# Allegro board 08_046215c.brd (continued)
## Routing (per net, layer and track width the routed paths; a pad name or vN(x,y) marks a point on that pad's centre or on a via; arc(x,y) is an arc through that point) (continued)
ADCLK914OUT: length 3.6
  TOP w0.305: U16.11 14.48,20.37 14.41,20.44 R625.1 14.41,23.33 C39.1
ADCLK914VCC: length 5.6
  TOP w0.254: R625.2 v1(15.05,21.99) ; U16.8 v1(16.88,19.13) 17.06,18.95 C654.1 ; U16.13 v1(12.58,19.13)
  TOP w0.305: C655.1 12.57,19.14 v1(12.58,19.13)
  BOTTOM w0.254: 11.43,7.32 v1(11.23,7.32)
  BOTTOM w0.508: 11.43,7.32 12.51,8.41 12.51,8.47 E68.2
ADF4355_VDD_3V3: length 16.4
  TOP w0.203: R619.2 31.37,9.87 v4(31.5,9.99) ; v1(24,16.09) 24,15.27 24.17,15.1 24.17,15.04 24.26,14.94 U15.5
  TOP w0.254: U15.16 22.06,10.08 v4(21.72,9.74) ; U18.2 12.82,12.54 12.15,13.21 11.85,13.21 ; v1(27.79,11.11) 27.72,11.11 27.64,11.19 27,11.19 U15.27 ; 11.85,13.21 C669.2 ; 11.85,13.21 v4(12.19,13.55)
  TOP w0.305: R611.2 v4(21.21,18.12)
  L10_SIGNAL w0.33: 43.26,14.65 JP1.2 ; JP1.2 44.87,14.65 ; JP1.2 44.87,16.26 ; JP1.2 43.26,16.26
  BOTTOM w0.254: C614.1 C616.1 26.61,10.91 26.96,11.26 27.56,11.26 27.71,11.11 v1(27.79,11.11)
  vias: v4(12.19,12.91)
ADF4355_VRF_3V3: length 1.7
  TOP w0.203: v4(21.21,14.12) 21.21,13.42 21.48,13.15
  TOP w0.305: U15.10 21.48,13.15
  vias: v4(16.26,11.01) v4(16.26,9.99)
ADF4355_VVCO_5V: length 10.2
  TOP w0.254: U15.19 23.76,8.74 23.37,8.34 C643.1 ; C618.1 23.05,16.03 23.5,15.58 23.5,15.2 23.76,14.93 U15.6
  TOP w0.305: U17.2 38.36,5.51 C668.2 ; C636.1 v4(22.1,8.47) 22.76,9.13 U15.17 ; C618.1 C619.1 v4(21.15,16.03)
  TOP w0.508: v4(39.37,5.29) 39.34,5.29 39.28,5.23 38.7,5.23 38.64,5.29 38.57,5.29 C668.2
  vias: v4(38.99,5.93)
ADF4355OUTA: length 1.6
  TOP w0.305: U16.2 14.48,15.64 C632.2
ADF4355OUTAB: length 1.6
  TOP w0.305: C633.2 13.98,15.66 U16.1
ADF4355OUTB: length 2.3
  TOP w0.305: U9.7 25.91,3.77 25.15,4.53 C638.2
ADF4355OUTBB: length 2.3
  TOP w0.305: U9.5 26.04,6.31 25.15,5.42 C639.2
ADP5054_1V2: length 5.7
  TOP w0.203: v6(29.83,40.58) U1.K9 v6(29.83,39.58) U1.K7 v6(29.83,38.58) ; v6(28.33,40.58) U1.G9 ; v6(28.33,39.08) U1.G6
  TOP w0.508: C525.1 v4(48.13,43.01)
  BOTTOM w0.254: C550.1 29.9,38.58 v6(29.83,38.58) ; C2.1 30,40.76 v6(29.83,40.58) ; C3.1 28.33,40.65 v6(28.33,40.58) ; v6(28.33,39.08) 28.33,38.52 C538.1 ; C544.1 v6(29.83,39.58)
  vias: v4(53.85,36.92) v4(54.1,37.68) v4(54.48,36.54)
ADP5054_1V5: length 2.7
  BOTTOM w0.508: 41.5,42.86 E1.2 v4(40.64,43.78) v4(40.64,44.66)
  vias: v4(22.61,60.92) v4(23.62,60.92) v4(24.13,60.16) v4(24.64,60.92) v4(31.88,60.79) v4(32.51,59.9) v4(33.02,60.79) v4(33.66,59.9) v4(38.35,43.64) v4(38.48,44.79) v4(41.53,42.89)
ADP5054_3V8: length 12.8
  TOP w0.508: 15.37,4.09 v4(16.19,4.09)
  L3_SIGNAL w0.508: v2(15.11,60.54) 13.46,60.54 12.83,59.9 v4(5.59,59.9)
  L11_GROUND w0.508: v3(15.11,61.3) v2(15.11,60.54)
  BOTTOM w0.508: 56.52,18.91 v4(56.52,18.25) ; R63.2 v3(15.11,61.3)
  vias: v4(5.59,60.67) v4(6.35,60.67) v4(9.02,15.45) v4(16.13,4.66) v4(39.24,63.08) v4(42.04,63.59) v4(55.44,18.63) v4(55.75,17.74) v4(56.64,17.36)
ADP5054_5V5: length 3.4
  TOP w0.508: 39.56,12.28 v4(40.26,12.28)
  BOTTOM w0.508: E31.1 v4(32.26,13.68) ; 36.09,22.69 34.42,22.69 v4(34.42,23.58)
  vias: v4(33.66,23.71) v4(40.26,12.91)
ADP5073_2V2: length 21
  BOTTOM w0.508: 36.45,51.52 35.05,52.92 35.05,53.68 32.77,55.97 29.59,55.97 25.4,60.16 25.4,61.56 24.38,62.57 R443.1
CLK_N: length 2.9
  TOP w0.254: U1.D1 26.83,35.52 arc(26.88,35.26) 27.03,35.03 27.18,34.89
  TOP w0.508: 27.18,34.89 27.37,34.69 arc(27.74,34.14) C349.2
CLK_P: length 2.9
  TOP w0.254: U1.C1 26.33,35.59 arc(26.25,35.21) 26.04,34.89
  TOP w0.508: 26.04,34.89 25.75,34.6 arc(25.42,34.1) C348.2
CPOUT: length 8.6
  TOP w0.203: U15.7 23.24,14.37 23.24,14.82 22.86,15.2 22.34,15.2 v1(22.09,14.95)
  BOTTOM w0.203: v1(22.09,14.95) 22.09,14.07 arc(22,13.59) 21.72,13.17 21.06,12.51 arc(20.66,12.25) 20.19,12.15 C61.2 C62.1 18.54,12.15 R62.1
CS1: length 67.2
  TOP w0.203: U21.14 57.29,45.31 56.29,44.31 56.29,44.06 v1(56.11,43.88) ; U20.20 v1(52.86,56.25)
  L3_SIGNAL w0.203: v1(56.11,43.88) 56.11,43.92 56.13,43.95 56.13,44.04 56.29,44.19 56.29,44.31 58.29,46.32 58.29,52.67 55.24,55.71 53.4,55.71 v1(52.86,56.25) 52.86,57.46 51.94,58.38 47.89,58.38 47.22,57.71 47.22,56.2 46.42,55.41 37.03,55.41 34.16,52.54 30.48,52.54 v1(28.7,50.76)
  L10_SIGNAL w0.203: v1(52.86,56.25) 52.86,57.97 50.93,59.9 50.93,62.25 50.61,62.57 49.4,62.57 46.84,65.14 44.17,65.14 P2.2
  BOTTOM w0.203: R19.1 v1(28.7,50.76)
CS2: length 79.5
  TOP w0.203: U22.11 63,43 62.48,43.52 61.47,43.52 61.15,43.84 v1(60.77,43.84) ; R316.1 52.5,7.25 v1(52.58,7.33) 52.58,5.73 52.45,5.6 52.45,5.29 R38.1 ; U20.10 v1(47.36,60.94)
  L10_SIGNAL w0.203: v1(60.77,43.84) 61.85,44.92 61.85,48.86 59.05,51.65 59.05,53.17 57.02,55.21 51.69,55.21 49.4,57.49 49.4,58.25 48.39,59.27 48.39,60.54 47.99,60.94 v1(47.36,60.94)
  BOTTOM w0.203: v1(60.77,43.84) 60.77,42.7 60.33,42.26
  BOTTOM w0.254: 60.33,42.26 60.33,39.58 60.96,38.95 60.96,30.95 60.33,30.31 60.33,13.04 57.66,10.37 54.36,10.37 52.58,8.6 v1(52.58,7.33)
CS3: length 88.9
  TOP w0.203: v1(51.56,64.22) U20.4 ; R615.1 v1(25.02,16.98) ; v1(63.75,41.87) 63.88,42 64.64,42 64.65,42 U22.13
  L3_SIGNAL w0.203: v1(51.56,64.22) 52.07,63.71 52.07,63.33 54.99,60.41 54.99,59.59 63.06,51.52 63.06,42.56 v1(63.75,41.87)
  L10_SIGNAL w0.203: v1(25.02,16.98) 25.02,18.25 28.07,21.3 30.73,21.3 31.71,22.28 46.05,22.28 46.74,21.59 56.26,21.59 63.12,28.45 63.12,33.36 64.39,34.63 64.39,41.24 v1(63.75,41.87)
DAC_CSB: length 5.8
  TOP w0.203: U1.G15 v6(28.33,44.53)
  L3_SIGNAL w0.203: v6(28.33,44.53) 28.33,47.72 v6(28.7,48.09)
  BOTTOM w0.203: R19.2 v6(28.7,48.09)
DAC_SCLK: length 7.4
  L3_SIGNAL w0.203: v6(29.33,42.08) 29.33,42.47 29.42,42.56 29.42,42.75 29.62,42.95 29.62,43.04 29.84,43.27 29.84,46.82 v6(30.99,47.97)
  BOTTOM w0.203: R23.2 30.99,48.47 v6(30.99,47.97)
DAC_SDIO: length 7.8
  L10_SIGNAL w0.203: v6(29.83,42.08) 29.93,42.08 30.42,42.57 30.42,42.75 30.73,43.06 30.73,43.33 30.74,43.33 30.74,43.67 30.73,43.67 30.73,45.43 v6(30.99,45.68)
  BOTTOM w0.203: R22.2 32.51,47.2 v6(30.99,45.68)
DAC_SDO: length 7.2
  L3_SIGNAL w0.203: v6(29.97,48.09) 28.83,46.95 28.83,44.28 28.32,43.78 28.32,42.89 28.62,42.58 v6(28.83,42.58)
  BOTTOM w0.203: v6(29.97,48.09) R20.2
DAC_TXEN_0: length 7.7
  TOP w0.203: v1(33.66,35.27) 34.34,35.27 R8.2
  L10_SIGNAL w0.203: v1(33.66,35.27) 32.77,34.38 30.92,34.38 29.92,35.38 29.92,35.49 v6(28.83,36.58)
  BOTTOM w0.203: R18.2 v1(33.66,35.27)
DIV2IN: length 1.4
  TOP w0.203: C341.2 46.74,6.35 46.87,6.48 U7.21
DIV2INB: length 1.4
  TOP w0.203: U7.22 47.37,6.44 47.5,6.31 C340.2
DL1: length 2.9
  BOTTOM w0.203: Q1.2 46.23,35.39 46.73,34.89 U10.31
DL2: length 5.7
  L10_SIGNAL w0.203: v1(46.23,38.19) 46.23,34.25 v1(45.97,34)
  BOTTOM w0.203: Q1.5 v1(46.23,38.19) ; U10.29 45.73,33.75 v1(45.97,34)
EN: length 32.1
  TOP w0.203: v5(11.4,64.12) Q3.PAD2 10.96,63.94 Q3.3 11.56,62.62 R51.1 ; v1(35.94,66.76) 35.94,66.13 35.37,65.55 U4.3
  L2_GROUND w0.203: v5(11.4,64.12) v2(11.94,63.59)
  L3_SIGNAL w0.203: v2(11.94,63.59) 12.19,63.33 13.59,63.33 14.1,63.84 15.75,63.84 16.89,62.7 20.28,62.7 20.5,62.93 28.3,62.93 32.13,66.76 v1(35.94,66.76)
FMC_CS1: length 5.6
  TOP w0.203: U21.3 61.73,45.31 62.36,45.93 v1(65.02,45.93)
  BOTTOM w0.203: P1.H11 65,45.93 v1(65.02,45.93)
FMC_CS2: length 4.8
  TOP w0.203: v1(68.88,45.86) 68.19,45.17 68.19,44.04 68.33,43.89 68.34,43.89 68.57,43.66 68.57,43.25 68.31,43 U22.6
  BOTTOM w0.203: P1.D11 v1(68.88,45.86)
FMC_CS3: length 2
  TOP w0.203: U22.4 68.83,42 v1(68.88,42.05)
  BOTTOM w0.203: P1.D14 v1(68.88,42.05)
FMC_HMC849VCTL: length 2.3
  TOP w0.203: U22.3 68.23,41.5 68.57,41.16 68.57,41.1 v1(68.88,40.78)
  BOTTOM w0.203: P1.D15 v1(68.88,40.78)
FMC_MISO: length 4.6
  TOP w0.203: v1(63.8,47.13) 62.03,47.13 61.21,46.31 U21.5
  BOTTOM w0.203: P1.H10 v1(63.8,47.13)
FMC_MOSI: length 6
  TOP w0.203: U21.4 61.35,45.81 62.13,46.6 64.19,46.6 64.21,46.62 64.55,46.62 v1(65.07,47.13)
  BOTTOM w0.203: P1.G10 v1(65.07,47.13)
FMC_SCK: length 6.1
  TOP w0.203: v1(65.07,48.4) 64.33,47.67 61.93,47.67 61.08,46.81 U21.6
  BOTTOM w0.254: P1.G9 v1(65.07,48.4)
FMC_SCL: length 36.3
  TOP w0.203: U23.6 71.81,54.51 73.79,52.54 73.79,24.09 73.28,23.58 72,23.58 v1(71.42,23)
  BOTTOM w0.203: P1.C30 v1(71.42,23)
FMC_SDA: length 37.6
  TOP w0.203: v1(70.15,23) 72,24.85 72.77,24.85 73.28,25.36 73.28,52.16 71.16,54.28 U23.5
  BOTTOM w0.203: v1(70.15,23) 70.15,21.73 P1.C31
FMC_SPI_EN: length 51.8
  TOP w0.203: U20.6 v1(50.26,64.19) ; v1(66.3,44.66) 66.17,44.66 65.6,45.23 65.6,48.62 65.24,48.98 64.26,48.98 63.5,49.74 59.31,49.74 R73.2 58.93,49.36 U21.9
  TOP w0.254: 63.5,45.05 63.88,45.05 64.13,45.3 65.53,45.3 65.6,45.23 ; U22.9 v1(66.3,44.66)
  L3_SIGNAL w0.203: v1(66.3,44.66) 66.94,45.3 68.17,45.3 v1(68.88,44.59)
  L10_SIGNAL w0.203: v1(50.26,64.19) 51.31,65.24 53.59,65.24 55.83,63 56.11,63 56.76,62.36 56.76,61.39 61.26,56.88 61.26,53.38 63.12,51.52 63.12,46.06 63.88,45.3 65.66,45.3 v1(66.3,44.66)
  BOTTOM w0.203: P1.D12 v1(68.88,44.59)
FMC_TXEN_0: length 8.8
  TOP w0.203: v1(70.23,43.27) 69.22,43.27 68.45,42.5 U22.5
  BOTTOM w0.203: P1.H13 65.11,43.29 68.49,43.29 68.51,43.27 69.25,43.27 69.27,43.29 69.76,43.29 69.78,43.27 v1(70.23,43.27)
FMCA_VCC_12P0V: length 18.1
  TOP w0.508: v4(56.39,9.1) D1.C v4(57.67,7.7) ; TP41.1 59.82,7.2 C548.P
  TOP w0.635: 58.97,8.63 TP41.1 ; TP41.1 58.97,10.34 ; TP41.1 60.67,10.34
  L5_POWER w0.635: 59.01,10.29 TP41.1 ; TP41.1 59.01,8.68 ; TP41.1 60.62,10.29
  BOTTOM w0.508: v4(56.26,5.17) 56.26,3.39 ; v1(71.5,16.72) 70.8,16.02 P1.C35 ; v1(70.12,14.3) 70.78,13.63 P1.C37 ; FL1.1 v4(54.24,3.28)
  vias: v4(54.48,1.74) v4(54.61,4.79) v4(55.5,1.61)
GA0: length 49.9
  TOP w0.203: U23.1 73.11,58.42 74.8,56.73 74.8,54.95 74.3,54.44 74.3,18.5 73.15,17.36 70.85,17.36 v1(70.15,16.65)
  BOTTOM w0.254: P1.C34 v1(70.15,16.65)
GA1: length 56.4
  TOP w0.203: U23.2 72.46,63.01 v1(72.39,63.08)
  L10_SIGNAL w0.203: v1(72.39,63.08) 72.39,56.1 75.46,53.03 75.46,19.04 73.79,17.36 69.8,17.36 69.6,17.16 69.6,16.1 v1(68.88,15.38)
  BOTTOM w0.254: P1.D35 v1(68.88,15.38)
GBTCLK0_M2C_N: length 72.7
  TOP w0.127: C333.2 51.65,8.47 51.84,8.66 53.38,8.66 54.68,9.96 54.68,11.29 54.48,11.5 54.48,11.59 54.28,11.79 53.92,11.79 v6(53.7,12.01)
  L3_SIGNAL w0.127: v6(53.7,12.01) 53.94,11.77 72.14,11.77 72.64,12.28 72.64,13.3 73.66,14.31 73.66,52.03 71.66,54.03 69.65,54.03 69.53,54.02 69.53,54.02 69.4,54 v1(68.88,53.48)
  BOTTOM w0.203: P1.D5 v1(68.88,53.48)
GBTCLK0_M2C_P: length 72.7
  TOP w0.127: C334.2 51.65,9.1 51.84,8.91 53.28,8.91 54.43,10.07 54.43,11.19 54.23,11.39 54.23,11.49 54.18,11.54 53.93,11.54 v6(53.7,11.31)
  L3_SIGNAL w0.127: v1(68.88,54.75) 69.37,54.26 69.5,54.27 69.64,54.28 71.77,54.28 73.91,52.14 73.91,14.21 72.9,13.19 72.9,12.17 72.24,11.52 53.91,11.52 v6(53.7,11.31)
  BOTTOM w0.203: P1.D4 v1(68.88,54.75)
HMC365_VDD: length 0.8
  BOTTOM w0.254: U6.2 30.09,6.57 30.1,6.56
  vias: v1(32,7.45)
HMC365OUT: length 21.2
  TOP w0.127: C341.1 46.74,5.08 46.99,4.82 46.99,3.9 46.48,3.39 R37.2 46.61,2.63 arc(46.88,2.52) 46.99,2.25 46.99,1.99 arc(46.96,1.85) 46.88,1.74 46.68,1.54 arc(46.62,1.5) 46.56,1.48 35.81,1.48 arc(35.28,1.71) 35.05,2.25 35.05,3.3 arc(34.88,3.72) 34.45,3.9 arc(34.19,3.95) 33.96,4.1 33.27,4.79 arc(32.99,4.97) 32.66,5.04 U9.3
HMC365OUTB: length 21.6
  TOP w0.127: C340.1 47.5,5.08 47.24,4.82 47.24,3.9 47.75,3.39 47.75,2.63 47.62,2.63 arc(47.36,2.52) 47.24,2.25 47.24,1.99 arc(47.2,1.76) 47.06,1.56 46.86,1.36 arc(46.72,1.26) 46.56,1.23 35.81,1.23 arc(35.1,1.53) 34.8,2.25 34.8,3.3 arc(34.7,3.54) 34.45,3.64 arc(34.19,3.59) 33.96,3.44 33.55,3.03 arc(32.96,2.64) 32.27,2.5 U9.1
HMC849_VDD: length 2
  BOTTOM w0.203: E66.2 12.51,10.63
  BOTTOM w0.508: 12.51,10.63 12.51,11.58 v1(11.94,12.15)
  vias: v1(19.69,22.95)
HMC849VCTL: length 87.3
  TOP w0.203: U22.14 64.4,41.5 v1(63.75,40.85) ; R31.2 v1(22.23,24.22) ; U20.9 v1(47.65,61.59)
  L3_SIGNAL w0.203: v1(63.75,40.85) 61.85,42.76 61.85,50 52.58,59.27 49.66,59.27 49.15,59.78 49.15,60.57 48.13,61.59 v1(47.65,61.59)
  L10_SIGNAL w0.203: v1(63.75,40.85) 63.75,34.76 62.36,33.36 62.36,29.42 57.15,24.22 54.09,24.22 54.07,24.19 53.63,24.19 53.6,24.22 39.24,24.22 39.03,24.43 33.24,24.43 33.02,24.22 v1(22.23,24.22)
IRQB: length 9.7
  TOP w0.203: U1.G1 28.33,34.5 30.35,32.47 TP21.1 31.12,29.81 CR5.C
LTC2928_ON: length 66.2
  L10_SIGNAL w0.203: v2(41.02,29.42) 39.62,30.82 38.73,30.82 37.47,32.09 31.68,32.09 28.32,35.45 28.32,36.92 28.83,37.43 28.83,37.62 27.92,38.53 27.92,40.75 28.32,41.15 28.32,43.52 27.43,44.41 27.43,45.55 28.07,46.19 28.07,51.87 24.73,55.21 20.45,55.21 18.41,53.17 17.02,53.17 16.13,54.06 14.52,54.06 13.59,53.13 11.6,53.13 10.92,53.81 5.84,53.81 4.45,55.21 v1(2.54,55.21)
  L11_GROUND w0.203: v3(41.53,28.93) 41.52,28.93 v2(41.02,29.42)
  BOTTOM w0.203: R70.2 v1(2.54,55.21) ; U10.17 v3(41.53,28.93) 40.88,28.93 R416.1
LTC2928_ON_A: length 67.6
  L10_SIGNAL w0.203: v1(51.05,46.7) 45.59,46.7 42.29,50 42.29,55.59 41.15,56.73 38.48,56.73 35.81,54.06 35.81,51.27 34.04,49.49 32.77,49.49 31.88,50.38 31.88,51.4 30.1,53.17 28.57,53.17 26.04,55.71 17.14,55.71 16.64,55.21 14.52,55.21 12.83,53.51 11.98,53.51 11.05,54.44 5.97,54.44 4.06,56.35 v1(2.54,56.35)
  BOTTOM w0.203: v1(51.05,46.7) 51.19,46.57 U11.3 ; R71.2 v1(2.54,56.35)
MISO: length 45.7
  TOP w0.203: U21.12 56.76,46.31 v1(56.13,45.68) ; U20.19 v1(52.21,56.49)
  L3_SIGNAL w0.203: v1(29.97,50.76) 31.24,52.03 34.54,52.03 36.32,53.81 39.12,53.81 39.88,53.05 41.28,53.05 43.05,54.82 46.86,54.82 47.88,55.84 47.88,56.35 48.51,56.98 49.3,56.98 50.19,57.87 51.69,57.87 52.21,57.35 v1(52.21,56.49) 52.21,55.83 53.09,54.95 55.24,54.95 57.66,52.54 57.66,47.2 v1(56.13,45.68)
  BOTTOM w0.203: R20.1 v1(29.97,50.76)
MOSI: length 140.8
  TOP w0.203: U20.18 v1(51.56,56.6) ; R36.1 50.93,4.91 50.93,5.29 51.5,5.87 R315.1 ; v1(55.69,45.1) 56.45,45.1 57.15,45.81 U21.13 ; R614.1 v1(26.54,16.41)
  TOP w0.254: v1(51.94,6.06) R315.1
  L3_SIGNAL w0.203: v1(26.54,16.41) 26.42,16.28 26.42,11.26 29.34,8.34 29.34,6.95 34.92,1.36 47.24,1.36 47.27,1.33 48.9,2.97 48.98,2.97 49.82,3.81 50.03,3.81 51.94,5.72 v1(51.94,6.06) 51.94,6.18 50.61,7.52 50.67,7.58 50.67,16.85 54.1,20.28 54.1,26.63 55.08,27.61 55.08,33.78 53.09,35.77 53.09,38.44 53.47,38.82 53.47,44.61 54.28,45.43 55.37,45.43 ; v1(55.69,45.1) 55.37,45.43 ; 55.37,45.43 55.37,45.93 55.72,46.28 55.97,46.28 57.02,47.33 57.02,52.28 55.12,54.19 52.83,54.19 51.56,55.46 v1(51.56,56.6)
  L10_SIGNAL w0.203: v1(32.51,50.76) 33.91,52.16 33.91,56.86 34.54,57.49 34.54,58.76 36.32,60.54 37.08,60.54 38.48,61.94 38.48,64.48 P2.1 43.68,63.09 47.74,63.09 49.02,61.81 49.02,60.16 51.56,57.62 v1(51.56,56.6)
  BOTTOM w0.203: R22.1 v1(32.51,50.76)
OUT_N: length 2.4
  TOP w0.762: T1.6 20.09,38.06 20.47,38.44 21.46,38.44
OUT_P: length 2.3
  TOP w0.762: 21.34,40.09 20.6,40.09 20.09,40.6 T1.4
PG_C2M: length 81.1
  L3_SIGNAL w0.203: v1(39.62,27.27) 40.51,28.15 v1(40.51,33.49) ; v1(68.88,58.56) 67.92,59.52 59.56,59.52 57.52,61.57 56.6,61.57 v1(55.96,62.22) ; v1(52.2,24.97) 52.2,31.96 v1(51.82,32.35) 51.82,39.46 52.32,39.97 52.32,47.33 53.09,48.09 53.09,48.98 v1(53.09,48.98)
  L10_SIGNAL w0.203: v1(52.2,24.97) 52.18,24.98 49.91,24.98 47.62,27.27 v1(39.62,27.27) ; v1(54.36,56.35) 54.36,60.62 v1(55.96,62.22)
  BOTTOM w0.203: v1(52.2,24.97) 51.96,24.73 R411.2 ; 52.7,49.87 53.09,49.49 v1(53.09,48.98) U11.6 ; 52.7,49.87 53.47,50.63 53.47,55.46 v1(54.36,56.35) ; 52.7,49.87 51.69,49.87 R436.1 ; v1(40.51,33.49) 40.26,33.23 R410.2 ; R412.2 v1(39.62,27.27) ; P1.D1 v1(68.88,58.56) ; R47.2 52.7,32.09 52.45,32.35 v1(51.82,32.35)
PGC: length 10.8
  TOP w0.203: v1(56.9,59.64) U20.24
  BOTTOM w0.203: v1(56.9,59.64) 57.15,59.89 57.15,63.71 54.48,66.38 XP1.3
PWRGD: length 64.2
  TOP w0.203: U20.28 54.54,64.03 v1(55.24,64.73) ; v1(18.16,64.35) 18.36,64.55 DS1.C
  L10_SIGNAL w0.203: v1(55.24,64.73) 55.24,67.02 54.48,67.78 39.24,67.78 37.47,66 32.44,66 30.15,63.71 27.43,63.71 26.8,64.35 v1(18.16,64.35) 14.61,64.35 13.59,63.33 12.37,63.33 12.14,63.1 11.74,63.1 11.51,63.33 6.35,63.33 4.7,61.68 v1(4.7,59.78)
  BOTTOM w0.203: v1(4.7,59.78) 5.08,59.4 5.21,59.4 5.48,59.12 U8.19
REF: length 2.1
  BOTTOM w0.203: U8.5 10.61,54.51 11.05,54.06 R75.2
REF_4355_N: length 13.3
  TOP w0.203: Y61.5 40.13,16.47 37.59,13.93 35.43,13.93 33.27,11.77 32.26,11.77 31.62,11.14 C610.1
REF_4355_P: length 9.6
  TOP w0.203: Y61.4 37.59,15.58 36.83,14.82 R65.1 34.67,14.57 33.66,13.55 33.15,13.55 32.26,12.66
SA_GND: length 7.8
  TOP w0.254: C32.7 6.63,31.96 6.58,31.91 6.43,31.91 v1(6.35,31.84) ; C32.1 8.76,31.46 v1(9.14,31.08) ; C33.5 8.76,45.68 v4(9.14,45.3) ; v4(9.53,46.95) 9.27,46.7 C33.7 ; C33.1 6.99,47.2 v4(6.48,47.71) ; v4(6.22,45.93) 6.48,46.19 C33.3 ; 9.65,32.47 C32.3 ; C32.5 6.73,32.98 v1(6.48,33.23)
  vias: v1(3.56,40.73) v1(3.56,37.93) v1(4.32,40.73) v1(4.32,37.93) v1(5.08,40.73) v1(5.08,37.93) v1(5.84,40.73) v1(5.84,37.93) v1(6.6,40.73) v1(6.6,37.93) v1(7.37,40.73) v1(7.37,37.93) v4(1.07,35.84) v4(1.07,34.31) v4(1.14,44.41) v4(1.14,42.89) v4(2.21,35.84) v4(2.21,34.31) v4(2.29,44.41) v4(2.29,42.89) v4(3.35,35.84) v4(3.35,34.31) v4(3.43,44.41) v4(3.43,42.89) v4(4.62,35.84) v4(4.62,34.31) v4(4.7,44.41) v4(4.7,42.89)
SCK: length 153.7
  TOP w0.203: v1(43.05,3.9) 43.05,4.41 R35.1 44.26,4.79 R314.1 ; R613.1 v1(27.18,16.98) ; v1(55.75,46.81) U21.11 ; U20.15 49.61,56.94 49.27,56.6 49.02,56.6 v1(48.77,56.35) 48.26,55.84 46.58,55.84 46.45,55.71 42.54,55.71 41.66,56.6 41.66,61.81 44.83,64.98 44.83,65.75 P2.3
  L3_SIGNAL w0.203: v1(43.05,3.9) 48.26,9.1 48.26,14.44 49.02,15.2 49.02,18.07 53.21,22.26 53.21,34.76 52.58,35.39 52.58,38.82 52.88,39.13 52.88,44.79 54.9,46.81 v1(55.75,46.81) ; v1(48.77,56.35) 48.77,55.47 47.62,54.32 43.69,54.32 41.78,52.41 39.75,52.41 38.86,53.3 36.83,53.3 34.92,51.4 31.88,51.4 v1(31.24,50.76)
  L10_SIGNAL w0.203: v1(27.18,16.98) 29.72,19.52 47.5,19.52 48.26,18.76 48.26,16.34 47.5,15.58 47.5,8.34 v1(43.05,3.9) ; v1(55.75,46.81) 56.15,47.2 56.64,47.2 57.53,48.09 57.53,53.05 56.13,54.44 50.16,54.44 48.77,55.83 v1(48.77,56.35)
  BOTTOM w0.203: R23.1 v1(31.24,50.76)
SERDIN0_N: length 6.1
  TOP w0.203: C816.1 32.5,47.83 29.81,45.13 29.81,43.51 29.83,43.49 U1.K15
SERDIN0_P: length 6.5
  TOP w0.203: U1.J15 29.33,43.49 29.35,43.51 29.35,45.32 32.27,48.25 32.27,48.32
SERDIN1_N: length 5.8
  TOP w0.203: U1.N15 31.33,43.49 31.31,43.51 31.31,44.48 32.89,46.06 34.86,46.06 C82.1
SERDIN1_P: length 6.5
  TOP w0.203: C81.1 34.94,46.52 32.7,46.52 30.85,44.67 30.85,43.51 30.83,43.49 U1.M15
SERDIN2_N: length 2.7
  TOP w0.203: U1.R12 32.34,41.58 32.94,41.58 32.95,41.58 34.67,41.58 34.76,41.49 C84.1
SERDIN2_P: length 2.7
  TOP w0.203: C83.1 34.49,42.12 34.46,42.09 32.74,42.09 32.73,42.08 U1.R13
SERDIN3_N: length 2.7
  TOP w0.203: U1.R9 32.34,40.08 32.34,40.08 34.54,40.08 34.66,39.97 C86.1
SERDIN3_P: length 2.7
  TOP w0.203: C85.1 34.98,40.59 32.34,40.59 U1.R10
SERDIN4_N: length 2.7
  TOP w0.203: C811.1 34.11,39.08 34.1,39.09 32.74,39.09 32.73,39.08 U1.R7
SERDIN4_P: length 2.7
  TOP w0.203: C812.1 34.68,38.44 34.54,38.58 32.74,38.58 32.73,38.58 U1.R6
SERDIN5_N: length 2.7
  TOP w0.203: C87.1 34.7,37.55 34.67,37.58 U1.R4
SERDIN5_P: length 2.7
  TOP w0.203: U1.R3 32.34,37.08 34.61,37.08 34.67,37.02 34.84,37.02 34.94,36.92 C88.1
SERDIN6_N: length 5.1
  TOP w0.203: U1.N1 31.33,35.68 31.31,35.66 31.31,35.25 32.57,34 34.86,34 C813.1
SERDIN6_P: length 5.8
  TOP w0.203: C814.1 34.94,33.54 32.38,33.54 30.85,35.06 30.85,35.66 30.83,35.68 U1.M1
SERDIN7_N: length 7.5
  TOP w0.203: C89.1 34.86,32.09 32.77,32.09 29.81,35.05 29.81,35.66 29.83,35.68 U1.K1
SERDIN7_P: length 8.2
  TOP w0.203: C810.1 34.94,31.63 32.58,31.63 29.35,34.86 29.35,35.66 29.33,35.68 U1.J1
SLEW: length 1.5
  BOTTOM w0.203: U11.2 50.91,46.07 50.9,46.06 R425.2
SPI33: length 1.8
  TOP w0.508: R6.1 R5.1 v4(32.64,27.9)
  vias: v4(26.29,62.32) v4(26.29,61.43) v6(29.83,37.08)
SUPPLY33: length 23.6
  TOP w0.203: U21.16 58.93,44.16 58.67,43.9 58.42,43.9
  TOP w0.254: U22.16 v1(66.3,39.72) ; v1(49.68,56.2) 50.27,56.2 50.91,56.84 U20.17
  TOP w0.305: U20.11 v1(47.75,60.29)
  TOP w0.508: C77.1 v1(66.3,39.72) ; C76.1 v1(57.66,43.9) 58.42,43.9 ; v1(63.12,64.22) 62.99,64.22 62.1,63.33 61.72,63.33 ; E32.2 v4(47.37,17.21) v4(47.37,17.84) v4(47.37,18.48) ; v4(60.13,61.87) XR2.1
  L8_POWER w0.635: XP1.2 52.29,65.53 ; XP1.2 50.58,67.23 ; XP1.2 50.58,65.53 ; XP1.2 52.29,67.23
  L11_GROUND w0.508: v3(17.14,57.24) v2(17.65,57.75)
  BOTTOM w0.508: R66.1 v3(17.14,57.24) ; XC4.P v1(63.12,64.22) ; R28.2 v4(46.33,64.3) ; XC6.1 v1(48.77,57.75) ; XC5.1 54.99,57.87 v1(55.24,57.62)
  vias: v1(30.35,62.95) v1(31.37,63.71) v1(31.37,62.95) v1(31.62,61.94) v1(32.51,61.94)
SVPLL12_EN: length 2
  TOP w0.203: U3.16 33.26,57.73 33.65,58.12 v1(33.66,58.12)
  BOTTOM w0.203: R338.2 32.89,58.89 v1(33.66,58.12)
SVSYN33_EN: length 1.6
  BOTTOM w0.203: U14.7 37.71,65.49 R339.2
SVSYNC33: length 2
  BOTTOM w0.305: C522.2 37.71,59.35 U14.2
  vias: v4(39.05,54.51) v4(40,54.51) v6(31.83,42.58) v6(31.83,36.58)
SW1: length 1
  BOTTOM w0.203: Q1.PAD1 46.88,36.98 Q1.6
SWITCH2BALUN: length 1
  TOP w0.381: R332.1 C38.1
SYNC_N: length 27.8
  TOP w0.127: v6(48.39,50.16) 48.61,50.38 51.31,50.38 51.94,49.74 SYNCN.1 JP34.1
  L3_SIGNAL w0.127: v6(48.39,50.16) 48.16,50.38 47.37,50.38 42.8,45.81 40.62,45.81 39.74,44.93 39.74,43.13 38.06,41.45 32.72,41.45 32.47,41.21 31.72,41.21 31.6,41.08 v6(31.33,41.08)
SYNC_P: length 27.9
  TOP w0.127: v6(48.39,50.86) 48.61,50.63 51.31,50.63 SYNCP.1 JP33.1
  L3_SIGNAL w0.127: v6(31.33,41.58) 31.55,41.58 31.68,41.46 32.37,41.46 32.61,41.71 37.96,41.71 39.49,43.24 39.49,45.03 40.51,46.06 42.69,46.06 47.3,50.67 48.2,50.67 v6(48.39,50.86)
SYSREF2_N: length 44.2
  TOP w0.127: v6(47.08,16.34) 46.86,16.12 46.86,14.25 C344.2 ; v6(56.27,51.66) 56.69,51.66 JP32.1
  L3_SIGNAL w0.127: v6(47.08,16.34) 46.86,16.57 46.86,16.92 46.81,16.98 46.81,18.71 46.86,18.76 46.86,19.92 50.04,23.1 50.04,46.72 51.94,48.62 51.94,50.15 53.7,51.9 56.03,51.9 v6(56.27,51.66)
SYSREF2_P: length 44.7
  TOP w0.127: C345.2 46.61,14.63 46.61,16.12 v6(46.39,16.34) ; v6(56.27,52.28) 56.71,52.28 JP31.1
  L3_SIGNAL w0.127: v6(56.27,52.28) 56.14,52.16 53.59,52.16 51.69,50.25 51.69,48.73 49.78,46.82 49.78,23.2 46.61,20.03 46.61,18.86 46.56,18.81 46.56,16.87 46.61,16.82 46.61,16.57 v6(46.39,16.34)
SYSREF_N: length 42.5
  TOP w0.127: v6(41.98,9.07) 42.2,8.85 42.58,8.85 42.58,8.85 42.71,8.85 42.96,9.1 C346.2
  L3_SIGNAL w0.127: v6(41.98,9.07) 41.93,9.02 41.41,9.02 41.02,9.4 41.02,10.12 42.04,11.14 42.04,13.55 42.93,14.44 42.93,17.08 41.91,18.1 41.91,23.07 43.48,24.65 43.48,32.27 41,34.76 38.59,34.76 37.85,35.5 37.85,35.83 v6(38.18,36.17)
  BOTTOM w0.127: v6(38.18,36.17) 38.09,36.17 37.85,36.41 34.43,36.41 32.88,37.95 31.6,37.95 31.47,38.08 v6(31.33,38.08)
SYSREF_P: length 43.3
  TOP w0.127: v6(41.98,8.37) 42.2,8.6 42.71,8.6 42.99,8.32 C347.2
  L3_SIGNAL w0.127: v6(41.98,8.37) 41.76,8.6 41.47,8.6 40.77,9.3 40.77,10.25 41.78,11.26 41.78,13.65 42.67,14.54 42.67,16.98 41.66,17.99 41.66,23.18 43.23,24.75 43.23,32.17 40.89,34.5 38.48,34.5 38.16,34.82 37.47,35.52 37.21,35.52 37.08,35.39 v6(37.08,35.27)
  BOTTOM w0.127: v6(37.08,35.27) 37.59,35.77 37.59,36.03 37.47,36.16 34.29,36.16 33.48,36.97 33.48,36.97 32.75,37.7 31.68,37.7 31.56,37.58 v6(31.33,37.58)
TOAD9508: length 22.6
  TOP w0.203: R329.1 v1(45.09,2.37) ; v1(30.73,15.58) R629.2
  L3_SIGNAL w0.203: v1(30.73,15.58) 30.99,15.33 30.99,13.51 34.12,10.37 34.12,9.65 41.53,2.25 44.7,2.25 44.83,2.37 v1(45.09,2.37)
TXEN_0: length 73.3
  TOP w0.203: U20.8 v1(47.54,62.24)
  TOP w0.254: U22.12 63.59,42.5 62.99,41.9 62.99,40.22 62.61,39.84 v1(60.96,39.84)
  L10_SIGNAL w0.203: v1(60.96,39.84) 60.96,38.19 59.82,37.04 58.17,37.04 56.64,35.52 50.16,35.52 47.37,32.73 38.48,32.73 v2(36.2,35.01) ; 60.71,42 62.48,43.78 62.48,49.24 59.82,51.9 59.82,55.08 57.18,57.72 v1(56.11,57.72)
  L10_SIGNAL w0.254: 60.71,42 60.33,41.62 60.33,40.47 v1(60.96,39.84)
  L11_GROUND w0.203: v3(35.69,34.5) v2(36.2,35.01)
  BOTTOM w0.203: v1(47.54,62.24) 55.07,62.24 55.98,61.33 55.98,59.86 56.12,59.73 56.12,57.85 56.11,57.84 v1(56.11,57.72) ; R18.1 v3(35.69,34.5)
UNNAMED_2_AD9162V4_I56_ISET: length 3
  TOP w0.203: R7.1 25.33,44.61 U1.A15
UNNAMED_2_AD9162V4_I56_PLLLDOBY: length 5.9
  TOP w0.203: v1(34.16,43.14) R21.2
  BOTTOM w0.203: v1(34.16,43.14) 33.66,42.63 33.66,40.35 33.4,40.09 32.51,40.09 32,39.58 v6(31.83,39.58)
UNNAMED_2_AD9162V4_I56_RESETN: length 10.9
  TOP w0.203: v1(31.5,29.04) R4.1
  BOTTOM w0.127: v6(29.33,37.08) 29.46,37.22 29.46,37.24 29.68,37.45 29.79,37.45 29.87,37.53
  BOTTOM w0.203: 29.87,37.53 29.89,37.55 30.48,37.55 31.42,36.61 31.42,35.92 31.46,35.88 31.46,29.08 v1(31.5,29.04)
UNNAMED_2_AD9162V4_I56_VBGNEG: length 0.1
  BOTTOM w0.203: C8.1 26.3,41.55 v6(26.33,41.58)
UNNAMED_2_AD9162V4_I56_VREF: length 2.6
  TOP w0.203: C23.1 25.83,45.6 U1.B15
UNNAMED_2_CAP_I33_N1: length 1.4
  TOP w0.203: R21.1 C21.1
UNNAMED_2_CAP_I39_N1: length 3.6
  TOP w0.203: R4.2 C7.1 R5.2 R3.1
UNNAMED_2_DIOLED_I48_P: length 2.7
  TOP w0.203: R6.2 34.96,27.18 CR5.A
UNNAMED_3_AD9508_I1155_EXTCAP1: length 2.2
  TOP w0.203: C325.2 50.97,10.63 50.45,10.11 U7.5
UNNAMED_3_AD9508_I1155_EXTCAP2: length 2.6
  TOP w0.203: C326.1 43.28,10.11 U7.14
UNNAMED_3_AD9508_I1155_INSEL: length 3.5
  TOP w0.203: U7.23 47.87,6.84 48.77,5.94 R39.1 R330.1
UNNAMED_3_AD9508_I1155_OUT0: length 1.7
  TOP w0.203: U7.2 50.22,8.61 50.36,8.47 C333.1
UNNAMED_3_AD9508_I1155_OUT0B: length 1.6
  TOP w0.203: C334.1 50.36,9.1 50.35,9.11 U7.3
UNNAMED_3_AD9508_I1155_OUT2: length 2.4
  TOP w0.203: U7.11 46.37,12.42 46.99,13.04 C344.1
UNNAMED_3_AD9508_I1155_OUT2B: length 2.2
  TOP w0.203: C345.1 46.1,12.91 45.85,12.66 45.85,11.38 U7.12
UNNAMED_3_AD9508_I1155_OUT3: length 1.5
  TOP w0.203: U7.16 43.63,9.11 C346.1
UNNAMED_3_AD9508_I1155_OUT3B: length 1.7
  TOP w0.203: U7.17 44.02,8.61 C347.1
UNNAMED_3_AD9508_I1155_RESETB: length 3.3
  TOP w0.203: U7.18 44.41,8.11 R311.2 43.43,7.01 R312.2
UNNAMED_3_AD9508_I1155_S0: length 2.2
  TOP w0.203: U7.19 44.58,6.07 R314.2
UNNAMED_3_AD9508_I1155_S1: length 3.3
  TOP w0.203: R315.2 49.28,6.06 48.37,6.97 U7.24
UNNAMED_3_AD9508_I1155_S2: length 2
  TOP w0.203: U7.1 49.95,8.11 50.74,7.33 R316.2
UNNAMED_3_AD9508_I1155_SYNCB: length 4.7
  TOP w0.203: 45.21,3.64 45.72,4.15 45.72,5.48 45.47,5.74 ; 45.47,5.74 46.37,6.64 U7.20 ; 45.47,5.74 R310.2
UNNAMED_3_ADM7150_I1277_BYP: length 1.8
  BOTTOM w0.203: C312.2 29.6,6.31 U6.3
UNNAMED_3_ADM7150_I1277_REF: length 0.6
  BOTTOM w0.203: U6.6 29.6,10.37 29.21,10.76
UNNAMED_3_ADM7150_I1277_VREG: length 5
  L3_SIGNAL w0.203: v1(33.78,6.18) 33.15,6.82 v1(31.12,6.82)
  BOTTOM w0.203: v1(31.12,6.82) 30.6,7.34 U6.1 ; v1(33.78,6.18) 33.44,6.18 C310.2
UNNAMED_3_CAP_I1148_N2: length 1.5
  TOP w0.305: U5.12 14.37,24 C39.2
UNNAMED_3_CAP_I1149_N2: length 1.4
  TOP w0.305: C34.2 U5.9
UNNAMED_3_CAP_I1150_N2: length 1.5
  TOP w0.203: 20.95,25.3 20.96,25.3 C38.2
  TOP w0.381: 20.95,25.3 U5.3
UNNAMED_3_CAP_I1305_N1: length 2.3
  TOP w0.686: C349.1 27.85,31.56 T33.6
UNNAMED_3_CAP_I1306_N1: length 2.3
  TOP w0.686: C348.1 25.31,31.59 T33.4
UNNAMED_3_CAP_I1318_N1: length 6
  TOP w0.686: J32.1 C14.1
UNNAMED_3_CAP_I1318_N2: length 8.4
  TOP w0.686: T1.1 T1.2 C14.2
UNNAMED_3_CNBNC5P_I1037_CNTR: length 13.1
  TOP w0.203: C34.1 13.59,25.95
  TOP w0.686: J31.1 4.89,21.8 arc(5.18,21.86) 5.43,22.03 8.97,25.57 arc(9.4,25.85) 9.91,25.95 12.89,25.95
UNNAMED_3_ICHMC849LP4CE_I1139_V: length 1.5
  TOP w0.305: U5.2 19.84,24.65 arc(20.41,24.54) R31.1
UNNAMED_3_RES_I1265_N2: length 2.5
  TOP w0.305: R332.2 23.75,25.36
  TOP w0.686: T33.3 25.31,25.74 24.93,25.36 23.75,25.36
UNNAMED_4_ADP5054_I1011_BST1: length 1.6
  BOTTOM w0.203: U10.32 47.23,34.37 47.5,34.63
UNNAMED_4_ADP5054_I1011_BST2: length 1.5
  BOTTOM w0.203: 45.21,34.63 45.23,34.61 U10.28
UNNAMED_4_ADP5054_I1011_BST3: length 1.6
  BOTTOM w0.203: U10.1 49.23,25.06 C413.1
UNNAMED_4_ADP5054_I1011_BST4: length 1.5
  BOTTOM w0.203: C415.1 43.73,24.94 U10.12
UNNAMED_4_ADP5054_I1011_CFG12: length 5.8
  BOTTOM w0.203: U10.18 41.96,29.43 41.2,30.19 R48.1 40.08,30.87 38.82,30.87 38.14,30.19 R41.2
UNNAMED_4_ADP5054_I1011_CFG34: length 2.9
  BOTTOM w0.203: U10.13 42.44,26.93 42.09,26.58 41.99,26.58 R49.1 R42.1
UNNAMED_4_ADP5054_I1011_COMP1: length 4.7
  BOTTOM w0.203: U10.40 50.72,30.93 50.87,30.77 53.47,30.77 53.77,31.08 R44.2
UNNAMED_4_ADP5054_I1011_COMP2: length 5.2
  BOTTOM w0.203: U10.20 42.43,30.43 41.87,30.99 41.87,30.99 41.16,31.71 39.2,31.71 R45.2
UNNAMED_4_ADP5054_I1011_COMP3: length 7.2
  L10_SIGNAL w0.203: v1(51.56,25.61) 52.04,25.61 52.16,25.5 52.42,25.5 52.43,25.49 53.85,25.49 54.23,25.11 v1(54.74,25.11)
  BOTTOM w0.203: U10.47 50.51,27.43 50.84,27.1 50.84,25.86 51.08,25.61 v1(51.56,25.61) ; R46.2 v1(54.74,25.11)
UNNAMED_4_ADP5054_I1011_COMP4: length 5.2
  BOTTOM w0.203: 37.85,27.9 39.65,27.9 39.7,27.95 42.09,27.95 42.14,27.9 42.95,27.9 U10.15
UNNAMED_4_ADP5054_I1011_EN1: length 1.5
  BOTTOM w0.203: U10.39 51.41,31.43 R47.1
UNNAMED_4_ADP5054_I1011_EN2: length 3
  BOTTOM w0.203: U10.21 42.48,30.93 41.53,31.88 R410.1
UNNAMED_4_ADP5054_I1011_EN3: length 2.2
  BOTTOM w0.203: R411.1 50.04,25.11 49.98,25.16 U10.48
UNNAMED_4_ADP5054_I1011_EN4: length 1.5
  BOTTOM w0.203: R412.1 41.69,27.43 U10.14
UNNAMED_4_ADP5054_I1011_FB1: length 18.3
  BOTTOM w0.203: R15.2 57.7,37.59 C11.1 56.9,37.59 56.77,37.46 R16.1 57.79,35.27 57.79,30.44 57.4,30.05 54.61,30.05 54.47,30.2 53.86,30.2 53.67,30.39 50.72,30.39 50.68,30.43 U10.41
UNNAMED_4_ADP5054_I1011_FB2: length 24.9
  L6_POWER w0.203: v1(36.96,31.08) 36.96,32.6 38.99,34.63 38.99,39.2 38.35,39.84 38.35,42.01 v1(37.47,42.9)
  BOTTOM w0.203: R1.1 R2.1 35.94,43.59 36.63,42.9 v1(37.47,42.9) 37.47,41.71 C13.1 ; v1(36.96,31.08) 37.13,31.25 40.97,31.25 42.3,29.93 U10.19
UNNAMED_4_ADP5054_I1011_FB3: length 2.8
  BOTTOM w0.203: U10.46 50.4,27.93 50.43,27.89 51.31,27.89 51.56,27.65 51.56,26.5
UNNAMED_4_ADP5054_I1011_FB4: length 8.7
  BOTTOM w0.203: U10.16 41.4,28.43 41.33,28.36 38.63,28.36 38.41,28.59 35.86,28.59 R423.1 R419.2
UNNAMED_4_ADP5054_I1011_RT: length 5.1
  BOTTOM w0.203: R413.1 54.23,29.3 53.84,29.69 53.72,29.69 53.4,30.01 50.49,30.01 50.48,30 50.05,30 U10.42
UNNAMED_4_ADP5054_I1011_SW31: length 1.8
  BOTTOM w0.203: U10.4 47.73,25.59 47.5,25.36 47.23,25.63 U10.5
UNNAMED_4_ADP5054_I1011_SW41: length 2
  BOTTOM w0.203: U10.8 45.73,25.86 45.23,25.36 ; U10.9 45.23,25.36 ; 45.23,25.36 45.23,25.25 45.21,25.23
UNNAMED_4_ADP5054_I1011_SYNC: length 1.7
  BOTTOM w0.203: 51.56,28.79 51.39,28.96 50.43,28.96 50.4,28.93 U10.44
UNNAMED_4_ADP5054_I1011_VDD: length 5.5
  BOTTOM w0.203: U10.43 50.8,29.43 50.95,29.57 53.28,29.57 53.38,29.47 53.39,29.47 53.56,29.31 53.58,29.31 54.01,28.88 54.01,28.77 54.18,28.61 54.28,28.61 C411.2
UNNAMED_4_ADP5073_I1002_COMP: length 3.5
  BOTTOM w0.203: U11.7 53.59,48.6 53.62,48.63 53.62,49.27 54.23,49.87 55.37,49.87
UNNAMED_4_ADP5073_I1002_FB: length 4.9
  BOTTOM w0.203: U11.8 54.09,48.21 54.61,48.73 R434.1 R430.2
UNNAMED_4_ADP7183_I808_VA: length 2.6
  BOTTOM w0.203: C435.1 C434.2 19.94,55.97 U12.3
UNNAMED_4_ADP7183_I808_VAFB: length 1.8
  BOTTOM w0.203: U12.4 19.44,56.74 C434.1
UNNAMED_4_ADP7183_I808_VREG: length 1.9
  BOTTOM w0.203: C427.2 20.44,60.92 U12.7
UNNAMED_4_CAP_I904_N2: length 23.9
  L10_SIGNAL w0.203: v1(60.07,48.6) 59.18,48.6 56.86,46.28 55.03,46.28 53.85,47.46 52.83,47.46 51.02,49.27 49.41,49.27 48.74,48.6 45.34,48.6 v1(43.31,50.63)
  BOTTOM w0.203: R430.1 59.05,48.09 59.56,48.09 v1(60.07,48.6) ; v1(43.31,50.63) D42.A
UNNAMED_4_CAP_I949_N2: length 5.6
  BOTTOM w0.203: 34.54,27.01 34.54,25.11 35.81,23.84 37.21,23.84 37.59,23.46
UNNAMED_4_CAP_I1000_N1: length 5.2
  BOTTOM w0.203: R437.2 54.23,51.4 55.63,52.79 56.77,52.79 57.15,52.41 57.15,51.14
UNNAMED_4_CAP_I1019_N2: length 1.7
  BOTTOM w0.203: C47.2 56.22,32.64 R44.1
UNNAMED_4_CAP_I1026_N2: length 1.7
  BOTTOM w0.203: R45.1 36.7,32.51 C48.2
UNNAMED_4_CAP_I1027_N2: length 1.3
  BOTTOM w0.203: R46.1 C49.2
UNNAMED_4_CAP_I1028_N2: length 1.8
  BOTTOM w0.203: C46.2 36.58,26.67 R43.1
UNNAMED_4_CAP_I1107_N2: length 1.4
  TOP w0.203: C18.2 R17.1
UNNAMED_4_DIOLED_I1138_N: length 2.3
  TOP w0.203: DS2.C 53.34,2.5 R417.2
UNNAMED_5_ADCLK914_I223_Q: length 4.3
  TOP w0.305: U16.12 13.98,20.01 arc(13.96,20.13) 13.89,20.24 13.14,20.98 R622.2
  TOP w0.33: R622.2 10.83,20.98 10.77,20.92 C4.1
UNNAMED_5_ADF4355_I299_CE: length 5.8
  TOP w0.203: U15.4 24.76,15.28 24.54,15.5 24.54,16.31 24.49,16.36 24.49,17.51 23.39,18.6 23.21,18.6 23.05,18.76 R611.1
UNNAMED_5_ADF4355_I299_CLK: length 1.9
  TOP w0.203: U15.1 26.26,14.98 R613.2
UNNAMED_5_ADF4355_I299_CREG2: length 2.3
  TOP w0.203: U15.32 v1(26.96,14.15)
  BOTTOM w0.203: C617.1 C612.1 26.81,13.5 26.81,13.61 26.96,13.77 v1(26.96,14.15)
UNNAMED_5_ADF4355_I299_DATA: length 1.5
  TOP w0.203: R614.2 25.76,15.62 U15.2
UNNAMED_5_ADF4355_I299_LE: length 1.5
  TOP w0.203: R615.2 25.26,15.53 U15.3
UNNAMED_5_ADF4355_I299_MUXOUT: length 2.2
  TOP w0.203: U15.30 27.42,12.65 27.69,12.91 27.69,13.42 27.94,13.68 28.38,13.68 R620.1
UNNAMED_5_ADF4355_I299_REFINA: length 4.2
  TOP w0.203: C611.2 R69.2 29.34,12.41 R612.1 28.32,12.15 U15.29
UNNAMED_5_ADF4355_I299_REFINB: length 3
  TOP w0.203: C610.2 R612.2 28.06,11.65 U15.28
UNNAMED_5_ADF4355_I299_RFOUTB: length 8.8
  TOP w0.305: U15.15 20.75,10.65 arc(20.49,10.6) 20.27,10.45 arc(20.12,10.23) 20.07,9.96 20.07,7.71 20.27,7.5 L64.1 20.27,6.3 20.05,6.08 20.05,5.6 20.37,5.28 R11.2 20.97,5.42 R13.1
UNNAMED_5_ADF4355_I299_RFOUTB_1: length 10.9
  TOP w0.305: U15.14 20.32,11.15 arc(19.98,11.08) 19.69,10.89 arc(19.5,10.6) 19.43,10.26 19.43,7.71 19.23,7.5 L63.2 19.23,6.3 19.44,6.08 19.44,5.28 20.08,4.65 R11.1 20.94,4.53 R12.1
UNNAMED_5_ADF4355_I299_RSET: length 1.6
  TOP w0.203: R618.1 25.23,8.3 25.23,8.96 25.26,9 U15.22
UNNAMED_5_ADF4355_I299_VBIAS: length 3.4
  TOP w0.203: U15.24 26.26,8.88 26.29,8.85 26.29,8.4 26.23,8.33 C637.1 v1(26.23,7.39)
  BOTTOM w0.203: C645.2 26.8,6.82 v1(26.23,7.39)
UNNAMED_5_ADF4355_I299_VREF: length 3.8
  TOP w0.203: U15.23 v1(25.76,8.62)
  BOTTOM w0.203: C648.1 25.21,8.72 25.66,8.72 v1(25.76,8.62) 25.78,8.6 25.78,7.7 25.69,7.61 25.69,7.33 C651.2
UNNAMED_5_ADM7150_I186_BYP: length 3.5
  TOP w0.203: C659.2 40.89,7.58 39.88,6.56 39.12,6.56 38.86,6.82 U17.3
UNNAMED_5_ADM7150_I186_REF: length 0.5
  TOP w0.203: U17.6 38.92,10.3 39.24,10.63
UNNAMED_5_ADM7150_I186_VREG: length 3.5
  TOP w0.203: U17.1 37.86,6.83 37.34,6.31 36.32,6.31 36.07,6.06 C656.2
UNNAMED_5_ADM7154_I181_BYP: length 1.6
  BOTTOM w0.203: U19.3 2.67,9.11 C661.2
UNNAMED_5_ADM7154_I181_VIN: length 0.9
  BOTTOM w0.203: 3.56,13.17 3.48,13.09 U19.7 3.17,13.42 3.3,13.55
UNNAMED_5_ADM7154_I181_VOUT: length 1
  BOTTOM w0.305: U19.2 3.17,9.36 3.3,9.23
UNNAMED_5_ADM7154_I181_VREG: length 2.2
  BOTTOM w0.203: C658.2 5.81,10.19 U19.1
UNNAMED_5_ADM7154_I297_BYP: length 3.3
  TOP w0.203: U18.3 12.32,11.19 12,11.51 10.28,11.51 C660.2
UNNAMED_5_ADM7154_I297_EN: length 0.9
  TOP w0.203: 13.08,7.07 12.82,7.33 U18.7
UNNAMED_5_ADM7154_I297_VREG: length 2.2
  TOP w0.203: v1(13.65,11.14) U18.1
  BOTTOM w0.203: v1(13.65,11.14) 14.83,12.32 C657.2
UNNAMED_5_CAP_I32_N2: length 2.3
  BOTTOM w0.203: R64.1 C66.2 R62.2
UNNAMED_5_CAP_I90_N1: length 10.4
  TOP w0.305: U15.12 18.9,12.15 arc(18.68,12.11) 18.5,11.98 arc(18.32,11.86) 18.11,11.82 L62.1 17.35,11.82 arc(16.98,12.07) 16.55,12.15 15.26,12.15 arc(14.77,12.25) 14.36,12.52 14.34,12.54 arc(14.07,12.95) 13.97,13.44 13.97,14.13 13.95,14.18 arc(13.93,14.22) 13.9,14.26 13.82,14.33 arc(13.74,14.45) 13.72,14.59 C633.1
UNNAMED_5_CAP_I203_N2: length 8.1
  TOP w0.203: C63.2 45.92,19.52 45.89,19.56 C65.2 43.87,19.56 42.76,18.45 Y61.6 42.58,18.45 41.55,17.42 41.55,17.33 41.53,17.31 JP1.1
UNNAMED_5_CAP_I269_N1: length 2.8
  TOP w0.203: U15.25 27.4,10.15 27.69,9.87 v1(27.69,9.23)
  BOTTOM w0.203: C620.1 C622.1 27.62,9.23 v1(27.69,9.23)
UNNAMED_5_CAP_I292_N1: length 1.7
  TOP w0.305: R12.2 23.13,4.53 R14.1 23.36,4.53 C638.1
UNNAMED_5_CAP_I293_N1: length 1.8
  TOP w0.305: R13.2 23.1,5.42 R14.2 23.38,5.42 C639.1
UNNAMED_5_CAP_I294_N1: length 9.6
  TOP w0.305: U15.11 18.5,12.65 arc(18.45,12.65) 18.4,12.67 18.39,12.67 arc(18.27,12.74) 18.17,12.82 18.07,12.91 arc(17.99,12.97) 17.89,12.99 L61.2 17.35,12.99 arc(16.98,12.75) 16.55,12.66 15.37,12.66 arc(14.74,12.92) 14.48,13.55 14.48,14.13 arc(14.51,14.3) 14.61,14.44 arc(14.7,14.58) 14.73,14.74 C632.1
UNNAMED_5_CAP_I329_N1: length 9.2
  TOP w0.203: L63.1 18.62,7.34 17.53,8.43 17.53,8.47 ; v1(18.29,5.93) 18.29,4.91 18.41,4.79
  TOP w0.254: C628.1 v1(21.34,7.07) 21.13,7.07 L64.2 ; L63.1 18.65,6.79 18.65,6.29 v1(18.29,5.93)
  L10_SIGNAL w0.203: v1(21.34,7.07) 20.5,6.23 19.08,6.23 18.77,5.93 v1(18.29,5.93)
UNNAMED_5_CAP_I349_N2: length 1.1
  BOTTOM w0.203: C62.2 R61.2
UNNAMED_5_CNBNC3P_I279_CNTR: length 11.6
  TOP w0.305: C4.2 9.27,20.92
  TOP w0.686: J62.1 4.95,13.61 arc(5.15,14.61) 5.72,15.45 arc(6.28,16.3) 6.48,17.29 6.48,17.85 arc(6.57,18.34) 6.85,18.75 8.84,20.74 arc(9.04,20.87) 9.27,20.92
UNNAMED_5_CNBNC3P_I308_CNTR: length 6.1
  TOP w0.203: J61.1 R629.1 R65.2
UNNAMED_5_DIOLED_I73_N: length 1.4
  TOP w0.203: DS61.C 24.85,20.32 R621.2
UNNAMED_5_DIOLED_I73_P: length 6
  TOP w0.203: R620.2 v1(28.45,15.33) ; v1(27.18,19.01) DS61.A
  BOTTOM w0.203: v1(28.45,15.33) 28.45,17.74 v1(27.18,19.01)
UNNAMED_5_FERRITE_I346_N1: length 1.8
  BOTTOM w0.203: E68.1 10.6,8.47
  BOTTOM w0.508: 10.6,8.47 R626.2
UNNAMED_5_FERRITE_I347_N1: length 1.8
  BOTTOM w0.203: E67.1 10.6,6.31
  BOTTOM w0.508: 10.6,6.31 R628.2
UNNAMED_5_FERRITE_I348_N1: length 1.8
  BOTTOM w0.203: E66.1 10.6,10.63
  BOTTOM w0.508: 10.6,10.63 R627.2
UNNAMED_5_RES_I49_N1: length 3.2
  TOP w0.203: U15.26 27.42,10.65 27.45,10.61 27.57,10.61 27.91,10.27 27.95,10.27 28.35,9.87 28.7,9.87 28.7,8.72
UNNAMED_6_CAP_I116_N2: length 2.7
  TOP w0.203: U20.3 v1(52.21,64.59)
  BOTTOM w0.203: v1(52.21,64.59) 52.16,64.54 XC12.2
UNNAMED_6_CN6P_I38_N1: length 13.4
  TOP w0.203: U20.25 v1(56.52,60.29)
  BOTTOM w0.203: XP1.1 50.14,65.14 53.82,65.14 56.52,62.44 v1(56.52,60.29)
UNNAMED_6_CN6P_I38_N5: length 9.3
  TOP w0.203: U20.26 57.93,60.94 XR2.2 59.05,62.06 XP1.5
UNNAMED_6_DIOLED_I258_N: length 3.3
  TOP w0.203: XCR1.C 55.12,56.73 54.54,57.31 U20.21
UNNAMED_6_DIOLED_I258_P: length 5.9
  TOP w0.203: XCR1.A 59.05,56.73 61.72,59.4 XR6.2
UNNAMED_6_ICPIC18F2XJ50_I109_OS: length 1.9
  TOP w0.203: U20.7 49.61,63.91 v1(49.25,64.27)
  BOTTOM w0.203: v1(49.25,64.27) 48.51,64.27 R28.1
UNNAMED_6_ICPIC18F2XJ50_I109_RC: length 2.5
  TOP w0.203: v1(47.75,57.49) 47.75,57.87 48.21,58.34 U20.14
  BOTTOM w0.203: v1(47.75,57.49) 47.62,57.36 47.62,56.6 R10.1
UNNAMED_7_CAP_I162_N2: length 45.3
  TOP w0.203: C811.2 35.74,38.96 39.74,38.96 59.92,18.78 71.01,18.78 v1(71.42,19.19)
  BOTTOM w0.203: P1.B32 v1(71.42,19.19)
UNNAMED_7_CAP_I163_N2: length 45.3
  TOP w0.203: C812.2 35.74,38.56 39.51,38.56 59.69,18.38 70.97,18.38 v1(71.42,17.92)
  BOTTOM w0.254: P1.B33 v1(71.42,17.92)
UNNAMED_7_CAP_I164_N2: length 45.5
  TOP w0.203: C813.2 35.67,34.07 38.54,34.07 59.12,13.5 69.79,13.5 70,13.71 71.01,13.71 v1(71.42,14.11)
  BOTTOM w0.254: P1.B36 v1(71.42,14.11)
UNNAMED_7_CAP_I165_N2: length 45.5
  TOP w0.203: C814.2 35.75,33.62 38.35,33.62 58.93,13.04 69.98,13.04 70.19,13.25 71.01,13.25 v1(71.42,12.84)
  BOTTOM w0.254: P1.B37 v1(71.42,12.84)
UNNAMED_7_CAP_I166_N2: length 44.4
  TOP w0.203: C82.2 35.71,46.02 42.2,46.02 57.28,30.95 72.36,30.95 v1(72.69,30.62)
  BOTTOM w0.203: P1.A23 v1(72.69,30.62)
UNNAMED_7_CAP_I167_N2: length 44.4
  TOP w0.203: C81.2 35.71,46.48 42.39,46.48 57.47,31.41 72.2,31.41 v1(72.69,31.89)
  BOTTOM w0.203: P1.A22 v1(72.69,31.89)
UNNAMED_7_CAP_I168_N2: length 44.6
  TOP w0.203: C84.2 35.71,41.58 43.73,41.58 55.88,29.42 59.44,29.42 62.99,25.87 72.36,25.87 v1(72.69,25.54)
  BOTTOM w0.254: P1.A27 v1(72.69,25.54)
UNNAMED_7_CAP_I169_N2: length 44.7
  TOP w0.203: v1(72.69,26.81) 72.2,26.33 63.18,26.33 59.63,29.88 56.07,29.88 43.92,42.04 35.71,42.04 C83.2
  BOTTOM w0.254: P1.A26 v1(72.69,26.81)
UNNAMED_7_CAP_I170_N2: length 46.1
  TOP w0.203: v1(72.69,20.46) 71.98,21.17 60.32,21.17 59.94,21.17 47.22,33.89 47.21,33.89 46.63,34.47 46.63,34.48 41.06,40.05 37.11,40.05 37.1,40.07 35.73,40.07 C86.2
  BOTTOM w0.203: P1.A31 v1(72.69,20.46)
UNNAMED_7_CAP_I171_N2: length 45.9
  TOP w0.203: v1(72.69,21.73) 72.09,21.73 71.98,21.63 60.13,21.63 47.41,34.35 47.4,34.35 47.09,34.66 47.09,34.67 41.25,40.51 37.3,40.51 37.29,40.53 35.7,40.53 C85.2
  BOTTOM w0.203: P1.A30 v1(72.69,21.73)
UNNAMED_7_CAP_I172_N2: length 47
  TOP w0.203: C88.2 35.71,37.01 38.65,37.01 59.69,15.96 69.34,15.96 69.72,15.58 72.49,15.58 v1(72.69,15.38)
  BOTTOM w0.254: P1.A35 v1(72.69,15.38)
UNNAMED_7_CAP_I173_N2: length 47.1
  TOP w0.203: v1(72.69,16.65) 72.07,16.04 69.91,16.04 69.53,16.42 59.88,16.42 38.84,37.46 35.71,37.46 C87.2
  BOTTOM w0.254: P1.A34 v1(72.69,16.65)
UNNAMED_7_CAP_I174_N2: length 48.2
  TOP w0.203: v4(74.04,11.64) 73.66,12.03 72.39,12.03 71.88,11.52 58.29,11.52 51.69,18.12 50.93,18.12 37.38,31.67 35.71,31.67 C810.2
  BOTTOM w0.254: v4(74.04,11.64) 73.34,10.94 P1.A39
UNNAMED_7_CAP_I175_N2: length 48.2
  TOP w0.203: C89.2 35.71,32.13 37.57,32.13 51.12,18.58 51.88,18.58 58.48,11.97 71.69,11.97 72.2,12.48 73.61,12.48 v4(74.04,12.91)
  BOTTOM w0.254: v4(74.04,12.91) 73.34,12.21 P1.A38
UNNAMED_7_CAP_I176_N2: length 41.5
  TOP w0.203: v1(70.15,56.02) 69.7,56.48 65.15,56.48 63.25,54.57 50.93,54.57 45.72,49.36 34.13,49.36 33.86,49.09 33.86,49.09 33.21,48.44 C816.2
  BOTTOM w0.203: P1.C3 v1(70.15,56.02)
UNNAMED_7_CAP_I177_N2: length 41.9
  TOP w0.203: C815.2 32.88,48.77 33.53,49.42 33.94,49.82 45.53,49.82 50.74,55.03 63.06,55.03 64.96,56.93 69.79,56.93 v1(70.15,57.29)
  BOTTOM w0.203: P1.C2 v1(70.15,57.29)
UNNAMED_7_CN400PAKV2_I143_LA01N: length 16.4
  TOP w0.203: v1(68.88,48.4) 68.78,48.4 67.56,49.62 64.39,49.62 63.63,50.38 55.05,50.38 JP34.2
  BOTTOM w0.254: P1.D9 v1(68.88,48.4)
UNNAMED_7_CN400PAKV2_I143_LA01P: length 16.1
  TOP w0.203: v1(68.88,49.67) 68.55,50 64.77,50 64.01,50.76 55.05,50.76 JP33.2
  BOTTOM w0.254: P1.D8 v1(68.88,49.67)
UNNAMED_7_CN400PAKV2_I143_TDI: length 1.3
  BOTTOM w0.203: P1.D30 P1.D31
UNNAMED_7_CN400PAKV2_I147_LA02N: length 8.7
  TOP w0.203: JP32.2 64.39,51.52 v1(65.02,50.89)
  BOTTOM w0.203: P1.H8 64.45,50.31 v1(65.02,50.89)
UNNAMED_7_CN400PAKV2_I147_LA02P: length 8.8
  TOP w0.203: JP31.2 59.94,52.41 60.33,52.79 64.39,52.79 v1(65.02,52.16)
  BOTTOM w0.254: P1.H7 64.45,51.58 v1(65.02,52.16)
UNNAMED_7_ICM24CXX_I210_E2: length 2.3
  TOP w0.203: R88.2 71.81,62.96 U23.3
UNNAMED_9_ADM7154_I249_BYP: length 2.9
  BOTTOM w0.203: U14.3 37.22,60.37 37,60.16 36.54,60.16 35.48,59.1 C515.1
UNNAMED_9_ADM7154_I249_REF: length 2.9
  BOTTOM w0.203: U14.6 37.22,64.35 36.96,64.6 36.7,64.6 ; U14.5 36.7,64.6 ; 36.7,64.6 36.45,64.86 36.45,65.37 C518.2
UNNAMED_9_ADM7154_I249_VREG: length 3.9
  BOTTOM w0.203: C514.1 39.74,58.85 38.22,60.37 U14.1
UNNAMED_9_ADM7154_I278_BYP: length 3.9
  TOP w0.203: C55.1 12.78,56.51 11.85,55.59 10.24,55.59 10.03,55.8 U13.3
UNNAMED_9_ADM7154_I278_REF: length 5.6
  TOP w0.203: U13.6 10.03,59.77 10.29,60.03 10.54,60.03 ; U13.5 10.53,60.02 10.54,60.03 ; 10.54,60.03 12.57,60.03 13.17,60.63 C510.2
UNNAMED_9_ADM7154_I278_VREG: length 3.4
  TOP w0.203: C51.1 7.75,54.52 9.03,55.8 U13.1
UNNAMED_9_ADP176X_I287_PG: length 1.7
  TOP w0.203: U2.15 23.62,57.23 24,57.62 R24.2
UNNAMED_9_ADP176X_I287_REFCAP: length 2.4
  TOP w0.203: U2.5 19.04,57.73 18.66,58.11 18.64,58.11 C25.1
UNNAMED_9_ADP176X_I287_SS: length 1.7
  TOP w0.203: U2.14 23.86,56.73 23.99,56.6 C22.1
UNNAMED_9_ADP176X_I287_VREG: length 2
  TOP w0.203: C30.1 18,57.23 U2.6
UNNAMED_9_ADP176X_I303_PG: length 1.7
  TOP w0.203: U3.15 34.16,57.23 R25.2
UNNAMED_9_ADP176X_I303_REFCAP: length 2.3
  TOP w0.203: C27.1 28.19,58.76 28.83,58.13 29.21,58.13 29.6,57.73 U3.5
UNNAMED_9_ADP176X_I303_SS: length 1.7
  TOP w0.203: U3.14 34.16,56.73 C24.1
UNNAMED_9_ADP176X_I303_VREG: length 1.9
  TOP w0.203: U3.6 28.16,57.23 C40.1
UNNAMED_9_CAPP_I31_N2: length 2
  TOP w0.203: C526.N R27.1
UNNAMED_10_CAP_I3_N1: length 1.9
  BOTTOM w0.203: U8.26 10.11,60.53 10.2,60.63 10.2,61.77 C64.1
UNNAMED_10_CAP_I4_N1: length 2.2
  BOTTOM w0.203: C60.1 11.3,61.8 10.92,61.42 10.92,60.98 10.61,60.66 U8.27
UNNAMED_10_CAP_I5_N1: length 2.4
  BOTTOM w0.203: C67.1 12.45,61.81 11.43,60.79 11.43,60.77 11.17,60.51 11.17,60.14 U8.28
UNNAMED_10_CAP_I7_N1: length 3.2
  BOTTOM w0.203: U8.23 8.61,61.1 8.76,61.25 8.76,61.68 R54.2 C57.1
UNNAMED_10_DIOLED_I29_P: length 1.5
  TOP w0.203: R327.2 DS1.A
UNNAMED_10_LINLTC2928_I1_DONEN: length 1.7
  BOTTOM w0.203: U8.18 4.72,58.62 R53.2
UNNAMED_10_LINLTC2928_I1_EN1: length 13.2
  TOP w0.203: Q2.2 v5(6.25,62.85)
  L2_GROUND w0.203: v5(6.25,62.85) 6.32,62.85 v2(6.73,62.44)
  L10_SIGNAL w0.203: v1(12.45,54.19) 12.45,56.22 8.13,60.54 8.13,61.81 7.49,62.44 v2(6.73,62.44)
  BOTTOM w0.203: v1(12.45,54.19) 12.11,54.53 U8.2
UNNAMED_10_LINLTC2928_I1_EN2: length 9
  TOP w0.203: Q3.2 v5(10.31,62.85)
  L2_GROUND w0.203: v5(10.31,62.85) 10.39,62.85 v2(10.79,62.44)
  L10_SIGNAL w0.203: v1(14.22,56.86) 14.22,57.75 10.79,61.17 v2(10.79,62.44)
  BOTTOM w0.203: U8.37 13.99,56.62 v1(14.22,56.86)
UNNAMED_10_LINLTC2928_I1_EN3: length 4.4
  TOP w0.203: Q4.2 14.38,62.85 v1(14.35,62.83)
  BOTTOM w0.203: U8.31 12.61,60.32 12.83,60.54 13.72,60.54 14.1,60.92 14.1,62.57 v1(14.35,62.83)
UNNAMED_10_LINLTC2928_I1_ON: length 4
  BOTTOM w0.203: U8.16 4.83,57.62 R68.2 R71.1 R70.1
UNNAMED_10_LINLTC2928_I1_OVA: length 4.1
  BOTTOM w0.203: R55.1 R76.1 14.96,54.57 12.95,54.57 12.61,54.92 U8.1
UNNAMED_10_LINLTC2928_I1_RT1: length 2
  BOTTOM w0.203: U8.6 10.11,54.15 9.91,53.95 R56.1
UNNAMED_10_LINLTC2928_I1_RT2: length 2.2
  BOTTOM w0.203: R58.1 8.76,53.81 9.61,54.65 U8.7
UNNAMED_10_LINLTC2928_I1_RT3: length 2.7
  BOTTOM w0.203: U8.8 9.11,54.79 8.5,54.19 8.12,54.19 7.62,53.69 R57.1
UNNAMED_10_LINLTC2928_I1_SQT1: length 4.2
  BOTTOM w0.203: R77.2 R78.1 6.47,53.3 6.47,53.94 6.62,54.09 7.44,54.09 8.11,54.75 U8.10
UNNAMED_10_LINLTC2928_I1_SQT2: length 5.6
  BOTTOM w0.203: R79.2 R80.1 4.19,53.4 5.26,54.47 7.28,54.47 7.61,54.79 U8.11
UNNAMED_10_LINLTC2928_I1_V1: length 4.1
  BOTTOM w0.203: U8.3 11.61,54.39 11.81,54.19 11.81,53.94 12.45,53.3 11.68,52.54 11.56,52.54 R75.1
UNNAMED_10_LINLTC2928_I1_V2: length 3
  BOTTOM w0.203: U8.38 15.09,56.12 R67.1 R66.2
UNNAMED_10_LINLTC2928_I1_V3: length 3
  BOTTOM w0.203: R59.2 R60.1 15.09,59.12 U8.32
UNNAMED_10_RES_I26_N1: length 45.3
  TOP w0.203: R50.1 6.9,62.15 Q2.3 6.9,63.94 Q2.PAD2 6.94,64.35 v1(7.4,64.35)
  L3_SIGNAL w0.203: v1(37.72,67.52) 31.88,67.52 v1(28.83,64.48) 27.81,63.46 21.08,63.46 20.57,63.97 19.43,63.97 v1(18.92,63.46) 16.89,63.46 15.62,64.73 11.81,64.73 10.54,63.46 8.29,63.46 v1(7.4,64.35)
  BOTTOM w0.203: R337.1 v1(18.92,63.46) ; v1(28.83,64.48) 28.83,61.56 R338.1 ; R339.1 v1(37.72,67.52)
UNNAMED_10_TRANNMOSFET2PAD_I17_: length 3.1
  TOP w0.203: Q4.PAD1 13.91,64.85 Q4.6 ; Q4.6 12.62,65.03 R29.2 ; Q4.6 Q4.5
UNNAMED_10_TRANNMOSFET2PAD_I21_: length 3.1
  TOP w0.203: Q3.6 9.66,64.71 9.68,64.7 9.68,64.32 9.85,64.15 Q3.PAD1 ; Q3.6 8.56,65.03 R40.2 ; Q3.6 Q3.5
UNNAMED_10_TRANNMOSFET2PAD_I24_: length 3.1
  TOP w0.203: R30.2 4.49,65.03 Q2.6 ; Q2.6 5.6,64.31 Q2.PAD1 ; Q2.6 Q2.5
USB_D+: length 4
  TOP w0.254: XP2.3 45.55,58.99 U20.13
USB_D-: length 5.1
  TOP w0.203: 46.05,59.64 45.19,60.49 45.16,60.49 44.49,60.49 44.48,60.5 XP2.2
  TOP w0.254: 46.05,59.64 U20.12
USB_VCC: length 8.4
  BOTTOM w0.203: 45.72,60.03 44.83,60.92 XP2.1
  BOTTOM w0.254: 45.72,60.03 46.99,58.76 46.99,58.38 47,58.38 47,56.22 46.99,56.22 46.99,55.84 R9.1
  BOTTOM w0.508: R9.1 46.61,55.21 R10.2
VADJ: length 23.8
  TOP w0.254: U22.7 67.84,43.81 67.78,43.87 67.78,44.32 v4(67.56,44.54) ; v4(65.02,44.54) 65.25,44.31 U22.10 63.77,43.5 R72.1 ; v4(59.82,43.65) 59.43,44.03 U21.1 60.31,44.27 60.48,44.43 U21.2 ; U21.7 60.48,47.61 v4(60.71,47.84) ; U21.15 57.56,44.81 v1(57.03,44.28) ; U22.2 67.84,39.99 67.56,39.71 v4(67.56,39.46) 66.8,40.22 U22.1 ; U22.15 65.25,40.83 v4(65.15,40.73)
  TOP w0.508: C72.1 60.71,42.76 v4(59.82,43.65) ; C71.1 67.06,45.81 67.56,45.3 v4(67.56,44.54) ; R73.1 v4(56.39,49.36)
  BOTTOM w0.254: P1.J39 v1(62.53,10.3) ; P1.H40 v1(63.8,9.03) ; P1.G39 v1(65.07,10.3) ; P1.E39 v1(67.61,10.3) ; P1.K40 v1(61.26,9.03)
  BOTTOM w0.508: v1(67.61,10.3) P1.F40 66.97,9.66 v1(66.29,8.98)
VNEG12: length 10.3
  TOP w0.508: R7.2 v4(24.26,47.59)
  L10_SIGNAL w0.635: TP43.1 21.68,45.46 ; TP43.1 19.98,45.46 ; TP43.1 21.68,47.17 ; TP43.1 19.98,47.17
  BOTTOM w0.254: C543.2 26.8,38.95 v6(26.92,39.08) ; v6(26.91,39.58) 26.74,39.58 C537.2 ; v6(26.33,42.58) 26.29,42.54 C8.2 ; C536.2 27.09,41.39 27.09,40.76 26.91,40.58 v6(26.33,40.58) ; C533.2 26.58,38.08 v6(26.33,38.08)
  BOTTOM w0.508: C549.2 16.32,50.72 v4(16.54,50.51)
  vias: v4(15.95,52.18) v4(16.51,51.45) v6(25.33,41.08) v6(25.33,37.58) v6(25.33,36.08) v6(26.33,40.08) v6(26.33,38.58)
VNEG12_EN: length 1.8
  BOTTOM w0.203: R337.2 19.44,60.65 U12.5
VOUT: length 11.9
  L6_POWER w0.203: v2(21.46,52.92) 15.37,52.92 14.99,52.54 14.99,51.65 14.48,51.14 v1(12.45,51.14)
  L11_GROUND w0.203: v3(21.46,53.68) v2(21.46,52.92)
  BOTTOM w0.203: R74.1 v1(12.45,51.14)
VREG: length 8.1
  L11_GROUND w0.203: v2(54.13,28.84) 54.13,27.65 53.98,27.49 v3(53.98,27.23) ; v3(50.65,28.43) 50.97,28.43 v2(51.26,28.71)
  BOTTOM w0.203: U10.45 v3(50.65,28.43) ; R414.1 52.96,28.79 53.98,27.77 v3(53.98,27.23) 54.14,27.23 54.36,27.01 C410.2
  BOTTOM w0.508: R49.2 v1(39.88,26.12) ; v1(38.99,29.04) R416.2 R48.2
VTUNE: length 9.1
  TOP w0.203: v1(24.06,7.52) 24.06,8.46 24.17,8.57 24.17,8.57 24.26,8.67 U15.20
  BOTTOM w0.203: R64.2 C69.2 18.58,7.45 19.13,8 21.16,8 21.64,7.52 v1(24.06,7.52)

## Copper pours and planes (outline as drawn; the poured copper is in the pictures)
GND on TOP: 9.02,65.49 9.02,55.21 27.69,55.21 27.69,65.49 ; 2 cut-outs
GND on TOP: 14.99,55.84 14.99,46.7 23.5,46.7 23.5,52.67 19.56,52.67 19.56,55.84
GND on TOP: outline of 88 points within 0.51,0.47 75.95,68.41 ; 21 cut-outs
GND on TOP: 0.51,65.49 0.51,48.73 9.78,48.73 9.78,52.67 9.02,52.67 9.02,57.11 9.78,57.11 9.78,65.49
GND on BOTTOM: 27.56,68.41 75.95,68.41 75.95,0.47 23.37,0.47 23.37,3.14 11.94,3.14 11.94,5.29 0.51,5.29 0.51,65.49 27.56,65.49 ; 12 cut-outs
